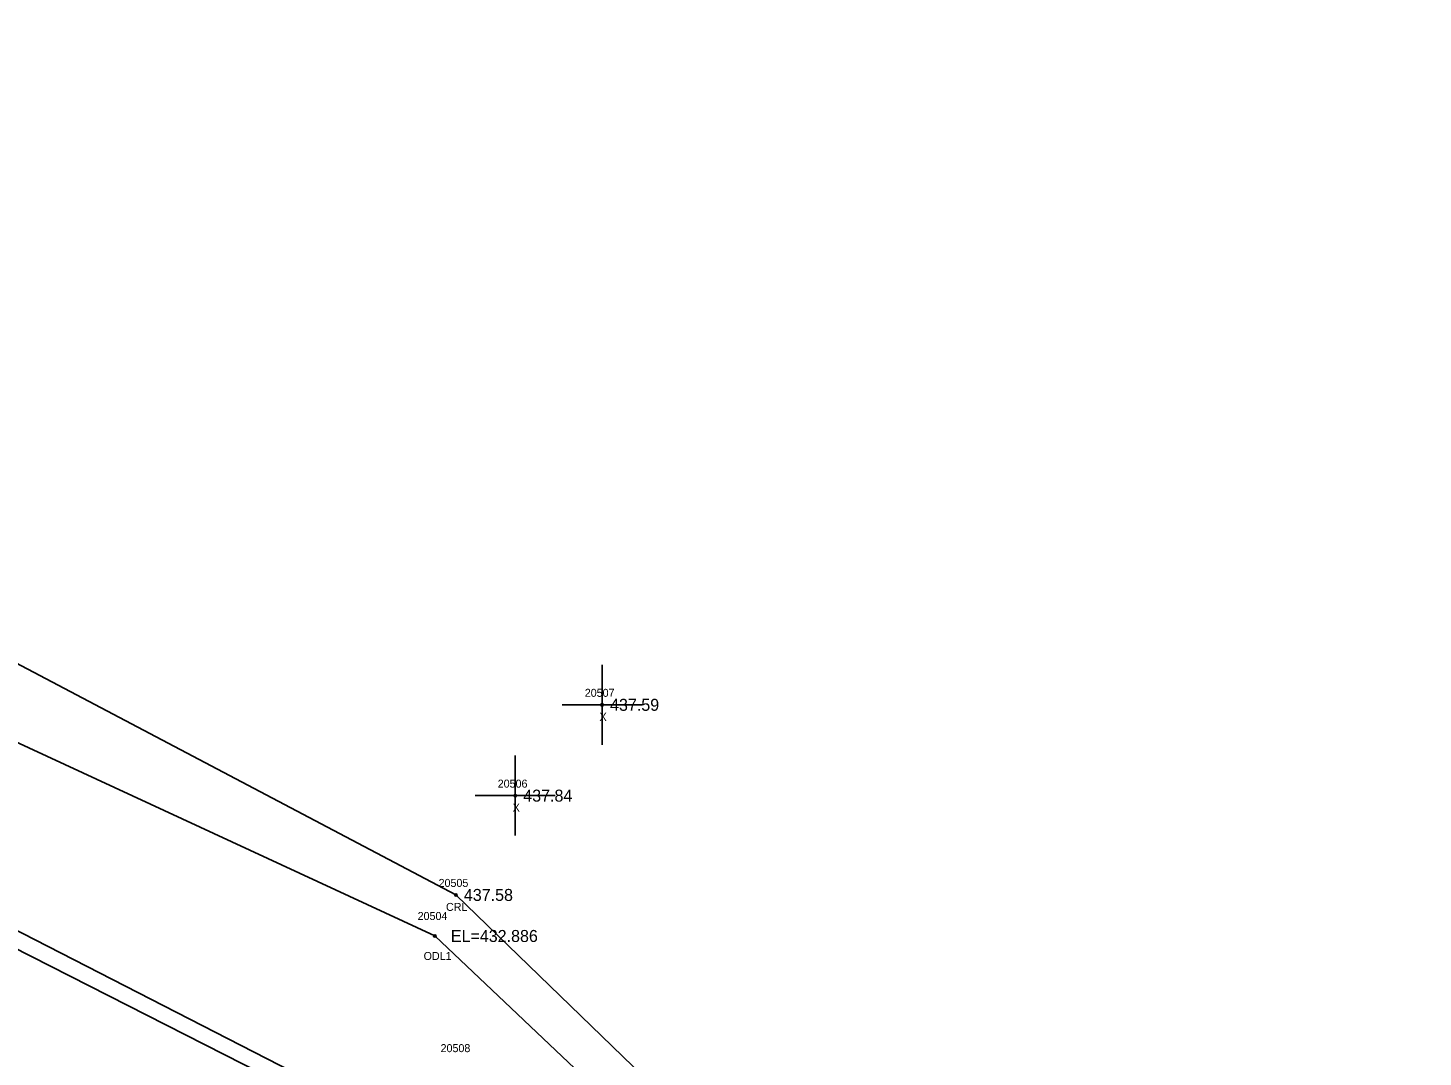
# Model space of a CAD drawing. Extents: x 1763022 to 1764007, y 824123 to 825394.
# Drawn here: x 1763608.9 to 1763783.3, y 824684.2 to 824812.8 of the extents above; entities that cross this region are included whole.
import ezdxf

# ---------------------------------------------------------------- set-up
doc = ezdxf.new("R2010")
doc.units = 0
for name, color, linetype in [('RD_EX_H2O', 7, 'Continuous'), ('RD_EX_H2O_txCode', 7, 'Continuous'), ('RD_EX_Misc', 7, 'Continuous'), ('RD_EX_Misc_txCode', 7, 'Continuous'), ('RD_EX_TX_H2O_ELEV', 7, 'Continuous'), ('RD_EX_TX_Misc_ELEV', 7, 'Continuous'), ('RD_SMD_Locator', 7, 'Continuous')]:
    doc.layers.add(name, color=color, linetype=linetype)

msp = doc.modelspace()

# ---------------------------------------------------------------- linework, layer by layer
at = {"layer": 'RD_EX_H2O'}
for points in [[(1763496.79, 824812.85), (1763505.69, 824806.42), (1763507.16, 824805.23), (1763521.58, 824789.49), (1763543.54, 824765.51), (1763572.14, 824752.09), (1763662.42, 824704.48), (1763697.56, 824670.47), (1763707.93, 824630.76), (1763723.52, 824595.87), (1763766.82, 824582.67), (1763818.29, 824585.49), (1763920.08, 824604.11)], [(1763494.44, 824810.56), (1763519.46, 824787), (1763539.48, 824759.37), (1763565.01, 824743.23), (1763659.79, 824699.35), (1763693.94, 824667), (1763705.55, 824629.75), (1763723.44, 824593.51), (1763767.2, 824575.02), (1763820.02, 824582.79), (1763920.83, 824600.99)], [(1763486.08, 824799.65), (1763514.15, 824779.95), (1763533.52, 824748.31), (1763547.12, 824731.03), (1763648.42, 824679.07), (1763662.67, 824682.83), (1763683.5, 824662.48), (1763694.46, 824627.33), (1763694.82, 824601.41), (1763712.85, 824586.53), (1763766.86, 824564.42), (1763816.87, 824572.85), (1763926.33, 824585.82)], [(1763485.59, 824798.12), (1763510.28, 824776.41), (1763530.73, 824746.57), (1763546.51, 824728.76), (1763647.95, 824677.16), (1763661.46, 824680.21), (1763679.15, 824659.29), (1763688.38, 824626.34), (1763689.04, 824599.45), (1763710.73, 824574.27), (1763740.3, 824562), (1763762.69, 824555.26), (1763820.3, 824563.65), (1763926.69, 824582.3)]]:
    msp.add_lwpolyline(points, dxfattribs=at)
at = {"layer": 'RD_EX_Misc'}
for p, q in [((1763680.69, 824723.24), (1763680.69, 824733.24)), ((1763675.69, 824728.24), (1763685.69, 824728.24)), ((1763669.84, 824711.89), (1763669.84, 824721.89)), ((1763664.84, 824716.89), (1763674.84, 824716.89))]:
    msp.add_line(p, q, dxfattribs=at)
at = {"layer": 'RD_SMD_Locator'}
for centre in [(1763680.69, 824728.24), (1763669.84, 824716.89), (1763662.42, 824704.48), (1763659.79, 824699.35)]:
    msp.add_circle(centre, 0.15, dxfattribs=at)

# ---------------------------------------------------------------- texts
at = {"layer": 'RD_EX_H2O_txCode'}
for s, p in [('20505', (1763660.26, 824705.48)), ('CRL', (1763661.19, 824702.48)), ('20504', (1763657.64, 824701.35)), ('ODL1', (1763658.39, 824696.35)), ('20508', (1763660.51, 824684.83))]:
    msp.add_text(s, height=1, dxfattribs=at).set_placement(p)
at = {"layer": 'RD_EX_Misc_txCode'}
for s, p in [('20507', (1763678.53, 824729.24)), ('X', (1763680.37, 824726.24)), ('20506', (1763667.65, 824717.89)), ('X', (1763669.52, 824714.89))]:
    msp.add_text(s, height=1, dxfattribs=at).set_placement(p)
at = {"layer": 'RD_EX_TX_H2O_ELEV'}
for s, p in [('437.58', (1763663.42, 824703.73)), ('EL=432.886', (1763661.79, 824698.6))]:
    msp.add_text(s, height=1.5, dxfattribs=at).set_placement(p)
at = {"layer": 'RD_EX_TX_Misc_ELEV'}
for s, p in [('437.59', (1763681.69, 824727.49)), ('437.84', (1763670.84, 824716.14))]:
    msp.add_text(s, height=1.5, dxfattribs=at).set_placement(p)

doc.saveas('drawing.dxf')
